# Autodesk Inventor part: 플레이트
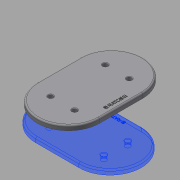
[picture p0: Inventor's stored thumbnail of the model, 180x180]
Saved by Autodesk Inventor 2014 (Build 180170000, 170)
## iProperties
Created: 2016-08
Part Number: 플레이트
Material: 알루미늄 6061
Document SubType Name: Modeling
Designer: mduedu
Density: 2.71 g/cm^3
Appearance: 기본값
Mass: 665.12 g
Surface Area: 557.689 cm^2
Volume: 245.432 cm^3
Author: mduedu
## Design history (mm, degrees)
sketch "스케치1" dims "d0" = 220, "d2" = 130
  geometry: L1 (45, 65)-(-45, 65); L2 (-45, 65)-(-45, -65); L3 (-45, -65)-(45, -65); L4 (45, -65)-(45, 65); L5 (45, 65)-(-45, -65); L6 (-45, 65)-(45, -65); 5 further points
  constraints: 12 end point, 5 midpoint, 2 parallel, 2 vertical alignment, 1 coincident, 1 horizontal, 1 perpendicular, 4 other
extrude "돌출1" new body sketch "스케치1" distance "d3" = 10; taper "d4" = 0 deg
sketch "스케치2"
  geometry: L1 (-57, -25)-(57, -25); L2 (57, -25)-(57, 25); L3 (57, 25)-(-57, 25); L4 (-57, 25)-(-57, -25); L5 (-57, -25)-(57, 25); L6 (57, -25)-(-57, 25); C1 r 5 at (-57, 25); C2 r 5 at (57, 25); C3 r 5 at (57, -25); C4 r 5 at (-57, -25); 1 further point
  constraints: 12 end point, 4 centre point, 4 coincident, 3 equal radius, 2 midpoint, 2 parallel, 1 horizontal, 1 perpendicular
  dimensions: "d5" = 114 distance of L2.end L3.end; "d7" = 50 distance of L1.end L2.end; "d8" = 10 diameter of C1
extrude "돌출2" cut sketch "스케치2" stored distance "d9" = 10; taper "d10" = 0 deg
chamfer "모따기1" distance "d11" = 1; stored, may be unused: second distance "d12" = 2, angle "d13" = 45 deg
fillet "모깎기1" dims "d14" = 3
sketch "스케치3"
  geometry: L1 (-45, -65)-(45, -65) reference; 2 further points
  constraints: 1 vertical alignment, 1 other
  dimensions: "d15" = 12 distance from line of point (0, -53) L1
feature "엠보싱1" sketch "스케치3" dims "d16" = 0.5, "d17" = 0
node "솔리드1"
